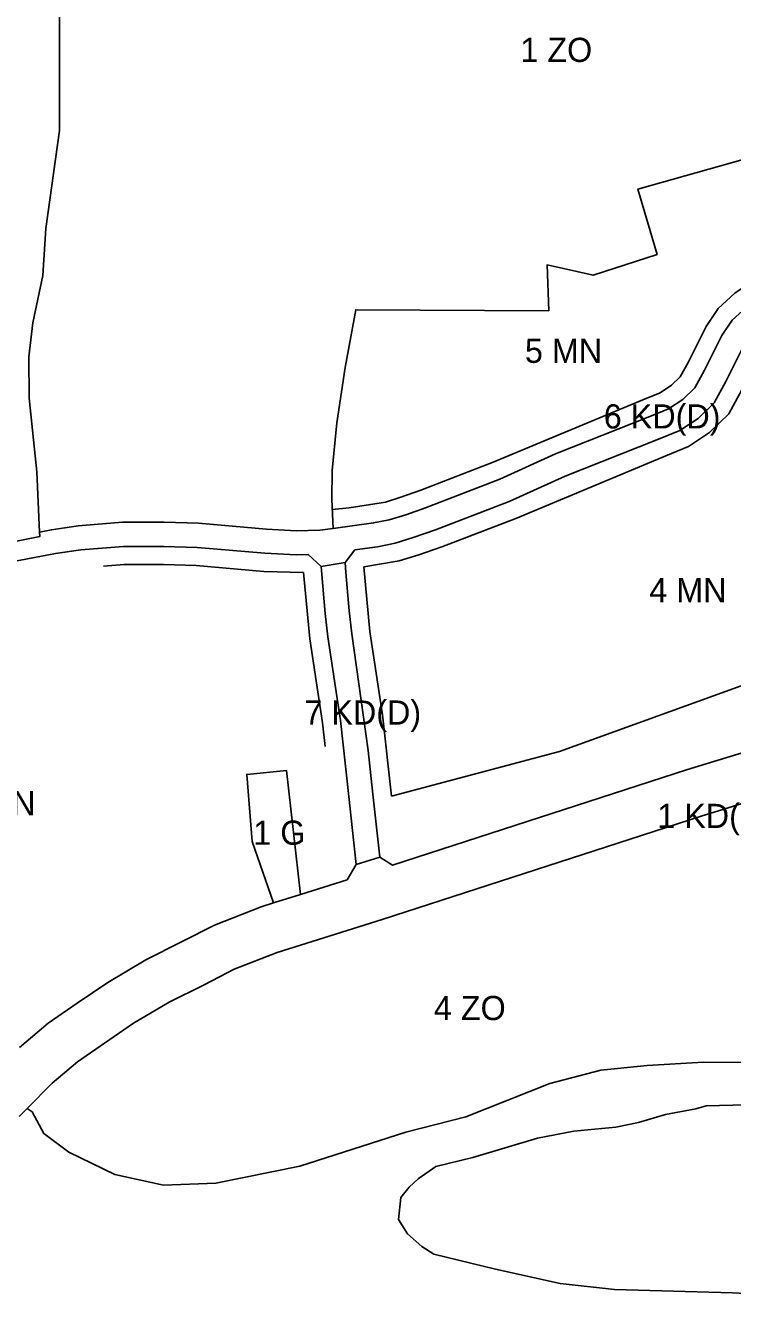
# Model space of a CAD drawing. Extents: x 7418056 to 7420315, y 5537846 to 5539505.
# Drawn here: x 7418557 to 7418849, y 5538515 to 5539041 of the extents above; entities that cross this region are included whole.
import ezdxf

# ---------------------------------------------------------------- set-up
doc = ezdxf.new("R2010")
doc.units = 0
for name, color, linetype in [('linie_rozgraniczajace', 7, 'Continuous'), ('linie_zabudowy_nieprzekraczalne', 7, 'Continuous'), ('oznaczenia_przeznaczen', 7, 'Continuous')]:
    doc.layers.add(name, color=color, linetype=linetype)

msp = doc.modelspace()

# ---------------------------------------------------------------- linework, layer by layer
at = {"layer": 'linie_rozgraniczajace'}
for points in [[(7418558.09, 5538886.78), (7418557.97, 5538903.92), (7418559.62, 5538918.05), (7418563.81, 5538937.62), (7418565, 5538957), (7418570.72, 5538997.62), (7418570.72, 5539007.61), (7418570.72, 5539047.36)], [(7418863.26, 5538988.38), (7418809.94, 5538973.34), (7418817.9, 5538946.33), (7418791.38, 5538937.74), (7418772.35, 5538941.99), (7418773.09, 5538923.05), (7418693.23, 5538923.46), (7418688.8, 5538899.48), (7418685.4, 5538876.61), (7418683.51, 5538856.86), (7418683.33, 5538844.86), (7418683.86, 5538832.94), (7418678.43, 5538832.24), (7418668.69, 5538832.01), (7418656.25, 5538832.67), (7418628.23, 5538835.08), (7418613.95, 5538835.53), (7418596.77, 5538835.51), (7418578.36, 5538834.08), (7418567.32, 5538832.42), (7418562.48, 5538831.44), (7418561.31, 5538856.34), (7418558.09, 5538886.78)], [(7418854.7, 5538924.41), (7418848.89, 5538919.08), (7418844.72, 5538912.79), (7418837.5, 5538898.38), (7418833.51, 5538891.11), (7418828.53, 5538886.31), (7418822.63, 5538882.4), (7418814.84, 5538879.23), (7418775.9, 5538863.8), (7418752.82, 5538853.31), (7418722.05, 5538841.49), (7418713.89, 5538838.63), (7418707.11, 5538836.53), (7418700.61, 5538835.25), (7418683.86, 5538832.94), (7418683.33, 5538844.86), (7418683.51, 5538856.86), (7418685.4, 5538876.61), (7418688.8, 5538899.48), (7418693.23, 5538923.46), (7418773.09, 5538923.05), (7418772.35, 5538941.99), (7418791.38, 5538937.74), (7418817.9, 5538946.33), (7418809.94, 5538973.34), (7418863.26, 5538988.38)], [(7418541.55, 5538825.46), (7418562.57, 5538829.66), (7418562.48, 5538831.44), (7418567.32, 5538832.42), (7418578.36, 5538834.08), (7418596.77, 5538835.51), (7418613.95, 5538835.53), (7418628.23, 5538835.08), (7418656.25, 5538832.67), (7418668.69, 5538832.01), (7418678.43, 5538832.24), (7418683.86, 5538832.94), (7418700.61, 5538835.25), (7418707.11, 5538836.53), (7418713.89, 5538838.63), (7418722.05, 5538841.49), (7418752.82, 5538853.31), (7418775.9, 5538863.8), (7418814.84, 5538879.23), (7418822.63, 5538882.4), (7418828.53, 5538886.31), (7418833.51, 5538891.11), (7418837.5, 5538898.38), (7418844.72, 5538912.79), (7418848.89, 5538919.08), (7418854.7, 5538924.41)], [(7418853.39, 5538907.77), (7418846.35, 5538893.73), (7418841.54, 5538884.97), (7418834.81, 5538878.47), (7418827.32, 5538873.51), (7418818.52, 5538869.94), (7418779.82, 5538854.6), (7418756.69, 5538844.08), (7418726.23, 5538832.38), (7418717.03, 5538829.13), (7418709.57, 5538826.82), (7418702.26, 5538825.38), (7418692.88, 5538824.08), (7418688.84, 5538818.78), (7418678.92, 5538817.26), (7418673.52, 5538822.13), (7418668.54, 5538822.01), (7418655.57, 5538822.68), (7418627.64, 5538825.09), (7418613.8, 5538825.53), (7418597.17, 5538825.52), (7418579.5, 5538824.14), (7418569.02, 5538822.56), (7418548.13, 5538818.52)], [(7418900.44, 5538754.64), (7418830.07, 5538733.01), (7418708.46, 5538693.58), (7418703.15, 5538696.97), (7418700.34, 5538723.05), (7418698.36, 5538741.02), (7418691.55, 5538789.39), (7418690.49, 5538798.78), (7418689.17, 5538814.7), (7418688.84, 5538818.78), (7418692.88, 5538824.08), (7418702.26, 5538825.38), (7418709.57, 5538826.82), (7418717.03, 5538829.13), (7418726.23, 5538832.38), (7418756.69, 5538844.08), (7418779.82, 5538854.6), (7418818.52, 5538869.94), (7418827.32, 5538873.51), (7418834.81, 5538878.47), (7418841.54, 5538884.97), (7418846.35, 5538893.73), (7418853.39, 5538907.77)], [(7418548.13, 5538818.52), (7418569.02, 5538822.56), (7418579.5, 5538824.14), (7418597.17, 5538825.52), (7418613.8, 5538825.53), (7418627.64, 5538825.09), (7418655.57, 5538822.68), (7418668.54, 5538822.01), (7418673.52, 5538822.13), (7418678.92, 5538817.26), (7418679.2, 5538813.88), (7418680.53, 5538797.8), (7418681.64, 5538788.08), (7418686.93, 5538753.49), (7418690.4, 5538721.97), (7418693.45, 5538693.85), (7418689.67, 5538687.56), (7418670.4, 5538681.48), (7418664.56, 5538732.79), (7418648.15, 5538731.15), (7418650.41, 5538703.43), (7418659.26, 5538677.97), (7418654.12, 5538676.35), (7418634.75, 5538668.8), (7418621.44, 5538661.99), (7418606.39, 5538654.45), (7418590.64, 5538645.11), (7418577.99, 5538636.51), (7418565.94, 5538628.18), (7418554.1, 5538618.12)], [(7418554.1, 5538618.12), (7418565.94, 5538628.18), (7418577.99, 5538636.51), (7418590.64, 5538645.11), (7418606.39, 5538654.45), (7418621.44, 5538661.99), (7418634.75, 5538668.8), (7418654.12, 5538676.35), (7418659.26, 5538677.97), (7418670.4, 5538681.48), (7418689.67, 5538687.56), (7418693.45, 5538693.85), (7418703.15, 5538696.97), (7418708.46, 5538693.58), (7418830.07, 5538733.01), (7418900.44, 5538754.64)], [(7418871.76, 5538724.9), (7418836.1, 5538713.94), (7418704.21, 5538671.17), (7418660.77, 5538657.48), (7418642.96, 5538650.52), (7418630.47, 5538644.15), (7418615.99, 5538636.89), (7418601.37, 5538628.22), (7418589.3, 5538620), (7418578.13, 5538612.29), (7418567.71, 5538603.44), (7418557.29, 5538592.89), (7418553.99, 5538589.55)], [(7418853.86, 5538611.94), (7418837.03, 5538612.11), (7418813.7, 5538610.75), (7418794.66, 5538608.76), (7418773.53, 5538603.22), (7418738.7, 5538589.42), (7418713.94, 5538583.13), (7418670.05, 5538569.11), (7418635.36, 5538562.02), (7418613.74, 5538561.17), (7418593.63, 5538565.64), (7418574.55, 5538574.82), (7418564.27, 5538582.53), (7418559.43, 5538591.48), (7418557.29, 5538592.89), (7418567.71, 5538603.44), (7418578.13, 5538612.29), (7418589.3, 5538620), (7418601.37, 5538628.22), (7418615.99, 5538636.89), (7418630.47, 5538644.15), (7418642.96, 5538650.52), (7418660.77, 5538657.48), (7418704.21, 5538671.17), (7418836.1, 5538713.94), (7418871.76, 5538724.9)], [(7418553.99, 5538589.55), (7418557.29, 5538592.89), (7418559.43, 5538591.48), (7418564.27, 5538582.53), (7418574.55, 5538574.82), (7418593.63, 5538565.64), (7418613.74, 5538561.17), (7418635.36, 5538562.02), (7418670.05, 5538569.11), (7418713.94, 5538583.13), (7418738.7, 5538589.42), (7418773.53, 5538603.22), (7418794.66, 5538608.76), (7418813.7, 5538610.75), (7418837.03, 5538612.11), (7418853.86, 5538611.94)], [(7418879.72, 5538515.1), (7418849.07, 5538516.69), (7418800.32, 5538518), (7418777.83, 5538520.55), (7418751.1, 5538526.4), (7418725.51, 5538532.61), (7418720.58, 5538535.86), (7418714.61, 5538541), (7418710.9, 5538546.99), (7418711.89, 5538556.05), (7418715.35, 5538560.41), (7418719, 5538563.85), (7418726.36, 5538568.88), (7418741.66, 5538572.66), (7418768.45, 5538580.67), (7418783.47, 5538583.49), (7418800.75, 5538585.13), (7418810.12, 5538587.09), (7418821.34, 5538590.38), (7418833.86, 5538592.78), (7418838.16, 5538594.04), (7418860.23, 5538594.58)], [(7418860.23, 5538594.58), (7418838.16, 5538594.04), (7418833.86, 5538592.78), (7418821.34, 5538590.38), (7418810.12, 5538587.09), (7418800.75, 5538585.13), (7418783.47, 5538583.49), (7418768.45, 5538580.67), (7418741.66, 5538572.66), (7418726.36, 5538568.88), (7418719, 5538563.85), (7418715.35, 5538560.41), (7418711.89, 5538556.05), (7418710.9, 5538546.99), (7418714.61, 5538541), (7418720.58, 5538535.86), (7418725.51, 5538532.61), (7418751.1, 5538526.4), (7418777.83, 5538520.55), (7418800.32, 5538518), (7418849.07, 5538516.69), (7418879.72, 5538515.1)]]:
    msp.add_lwpolyline(points, dxfattribs=at)
for points in [[(7418678.92, 5538817.26), (7418688.84, 5538818.78), (7418689.17, 5538814.7), (7418690.49, 5538798.78), (7418691.55, 5538789.39), (7418698.36, 5538741.02), (7418700.34, 5538723.05), (7418703.15, 5538696.97), (7418693.45, 5538693.85), (7418690.4, 5538721.97), (7418686.93, 5538753.49), (7418681.64, 5538788.08), (7418680.53, 5538797.8), (7418679.2, 5538813.88)], [(7418648.15, 5538731.15), (7418664.56, 5538732.79), (7418670.4, 5538681.48), (7418659.26, 5538677.97), (7418650.41, 5538703.43)]]:
    msp.add_lwpolyline(points, close=True, dxfattribs=at)
at = {"layer": 'linie_zabudowy_nieprzekraczalne'}
for points in [[(7418881.89, 5538946.72), (7418871.38, 5538941.95), (7418858.22, 5538935.79), (7418850.06, 5538930.32), (7418843.14, 5538924), (7418838.22, 5538916.56), (7418830.85, 5538901.86), (7418827.48, 5538895.72), (7418823.82, 5538892.18), (7418819.12, 5538889.07), (7418811.92, 5538886.15), (7418750.1, 5538860.3), (7418720.17, 5538848.81), (7418711.52, 5538845.75), (7418705.48, 5538843.88), (7418690.55, 5538841.44), (7418683.51, 5538840.72)], [(7418914.52, 5538934.66), (7418899.46, 5538927.23), (7418881.84, 5538919.25), (7418870.55, 5538913.97), (7418865.54, 5538910.61), (7418862.29, 5538907.63), (7418859.89, 5538904.01), (7418852.99, 5538890.25), (7418847.58, 5538880.37), (7418839.53, 5538872.6), (7418830.83, 5538866.85), (7418821.44, 5538863.04), (7418759.41, 5538837.1), (7418728.82, 5538825.35), (7418719.39, 5538822.02), (7418711.22, 5538819.48), (7418696.52, 5538817.09)], [(7418671.64, 5538814.68), (7418655.17, 5538815.19), (7418627.2, 5538817.61), (7418613.69, 5538818.03), (7418597.46, 5538818.02), (7418588.92, 5538817.36)], [(7418696.52, 5538817.09), (7418699.01, 5538790.26), (7418704.28, 5538755.77), (7418707.95, 5538722.19)], [(7418671.64, 5538814.68), (7418674.18, 5538787.22), (7418679.49, 5538752.52), (7418680.57, 5538742.67)], [(7418707.95, 5538722.19), (7418777.45, 5538740.64), (7418852.61, 5538767.82), (7418947.43, 5538802.58)]]:
    msp.add_lwpolyline(points, dxfattribs=at)

# ---------------------------------------------------------------- texts
at = {"layer": 'oznaczenia_przeznaczen'}
for s, p in [('1 ZO', (7418761.33, 5539025.97)), ('5 MN', (7418763.2, 5538901.45)), ('6 KD(D)', (7418795.81, 5538874.31)), ('4 MN', (7418814.64, 5538802.4)), ('7 KD(D)', (7418671.99, 5538751.77)), ('6 MN', (7418528.82, 5538714.23)), ('1 KD(Z)', (7418817.93, 5538709.01)), ('1 G', (7418650.87, 5538702.04)), ('4 ZO', (7418725.54, 5538629.51))]:
    msp.add_text(s, height=10, dxfattribs=at).set_placement(p)

doc.saveas('drawing.dxf')
